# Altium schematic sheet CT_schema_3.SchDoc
size 411 x 401 mm
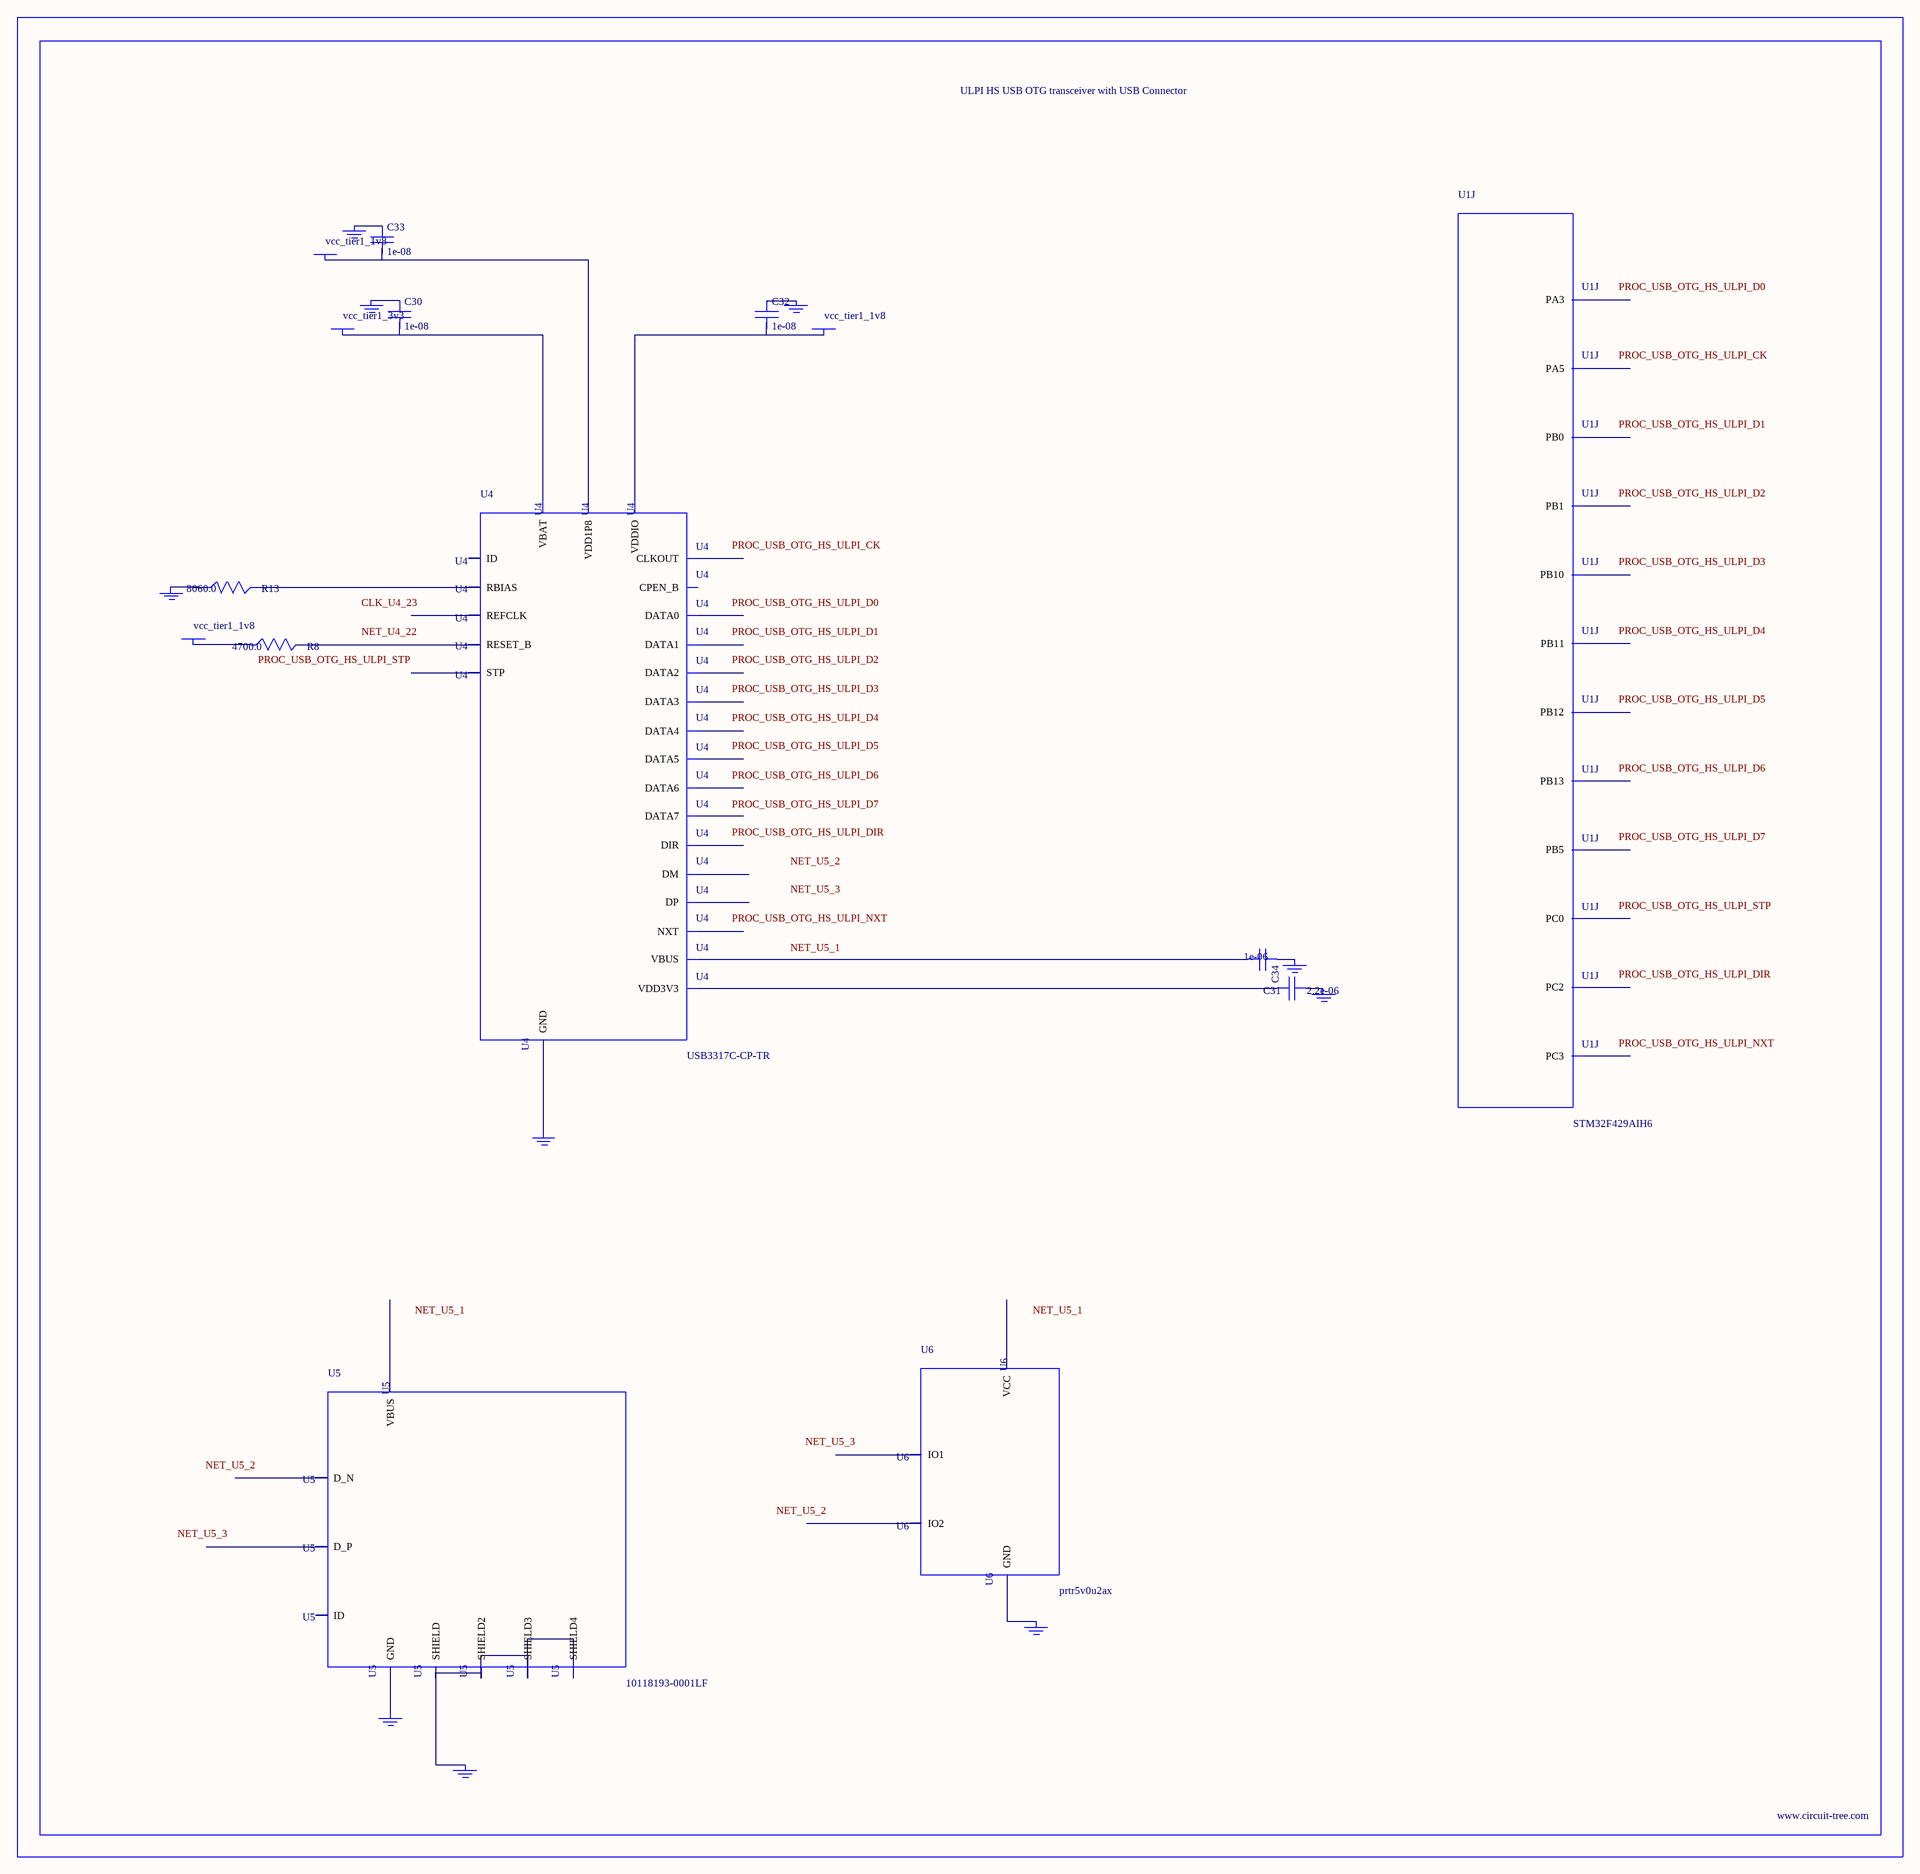
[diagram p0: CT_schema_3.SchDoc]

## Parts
BORDER2  (no value)
C30  1e-08  [C0402]
C31  2.2e-06  [C0603]
C32  1e-08  [C0402]
C33  1e-08  [C0402]
C34  1e-06  [C0603]
GND_INSTANCE_2_0  (no value)
GND_INSTANCE_2_1  (no value)
GND_INSTANCE_2_2  (no value)
GND_INSTANCE_2_3  (no value)
GND_INSTANCE_2_4  (no value)
GND_INSTANCE_2_5  (no value)
GND_INSTANCE_2_6  (no value)
GND_INSTANCE_2_7  (no value)
GND_INSTANCE_2_8  (no value)
GND_INSTANCE_2_9  (no value)
POWER_INSTANCE_2_0  vcc_tier1_3v3
POWER_INSTANCE_2_1  vcc_tier1_1v8
POWER_INSTANCE_2_2  vcc_tier1_1v8
POWER_INSTANCE_2_3  vcc_tier1_1v8
R8  4700.0  [R0603]
R13  8060.0  [R0603]
U1  STM32F429AIH6  [UFBGA169]  (part J of 12)
U4  USB3317C-CP-TR  [QFN-24]
U5  10118193-0001LF  [FCI_10118193-0001LF]
U6  prtr5v0u2ax  [SOT143B]

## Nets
NetC30_1: C30.1 GND_INSTANCE_2_1.0(GND)
NetC30_2: C30.2 POWER_INSTANCE_2_0.0(PWR) U4.3(VBAT)
NetC31_1: C31.1 GND_INSTANCE_2_2.0(GND)
NetC31_2: C31.2 U4.4(VDD3V3)
NetC32_1: C32.1 GND_INSTANCE_2_3.0(GND)
NetC32_2: C32.2 POWER_INSTANCE_2_1.0(PWR) U4.17(VDDIO)
NetC33_1: C33.1 GND_INSTANCE_2_4.0(GND)
NetC33_2: C33.2 POWER_INSTANCE_2_2.0(PWR) U4.21(VDD1P8)
NetC34_1: C34.1 GND_INSTANCE_2_0.0(GND)
NetC34_2: C34.2 U4.2(VBUS)
NetGND_INSTANCE_2_5_0: GND_INSTANCE_2_5.0(GND) R13.1
NetGND_INSTANCE_2_6_0: GND_INSTANCE_2_6.0(GND) U4.25(GND)
NetGND_INSTANCE_2_7_0: GND_INSTANCE_2_7.0(GND) U5.6(SHIELD) U5.7(SHIELD2) U5.8(SHIELD3) U5.9(SHIELD4)
NetGND_INSTANCE_2_8_0: GND_INSTANCE_2_8.0(GND) U5.5(GND)
NetGND_INSTANCE_2_9_0: GND_INSTANCE_2_9.0(GND) U6.1(GND)
NetPOWER_INSTANCE_2_3_0: POWER_INSTANCE_2_3.0(PWR) R8.1
NetR8_2: R8.2 U4.22(RESET_B)
NetR13_2: R13.2 U4.24(RBIAS)

Not connected (* = marked no-connect by the designer): U1 D5(PB5) G6(PC0) H6(PC2) H7(PC3) K3(PA3) K5(PB1) L9(PB10) M3(PA5) M9(PB11) M12(PB13) N4(PB0) N12(PB12); U4 1(ID) 5(DM) 6(DP) 7(CPEN_B) 8(DATA7) 9(DATA6) 10(DATA5) 11(DATA4) 12(CLKOUT) 13(DATA3) 14(DATA2) 15(DATA1) 16(DATA0) 18(NXT) 19(DIR) 20(STP) 23(REFCLK); U5 1(VBUS) 2(D_N) 3(D_P) 4(ID); U6 2(IO1) 3(IO2) 4(VCC)

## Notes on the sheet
- Labels drawn without touching a wire or pin: CLK_U4_23, NET_U4_22, NET_U5_1, NET_U5_2, NET_U5_3, PROC_USB_OTG_HS_ULPI_CK, PROC_USB_OTG_HS_ULPI_D0, PROC_USB_OTG_HS_ULPI_D1, PROC_USB_OTG_HS_ULPI_D2, PROC_USB_OTG_HS_ULPI_D3, PROC_USB_OTG_HS_ULPI_D4, PROC_USB_OTG_HS_ULPI_D5, PROC_USB_OTG_HS_ULPI_D6, PROC_USB_OTG_HS_ULPI_D7, PROC_USB_OTG_HS_ULPI_DIR, PROC_USB_OTG_HS_ULPI_NXT, PROC_USB_OTG_HS_ULPI_STP

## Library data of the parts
BORDER2 = BORDER_PAGE2
C30 C32 C33 = C0402C103K3RAC
C31 = C0603C225K8RACTU
C34 = C0603C105K3RACTU
GND_INSTANCE_2_0-GND_INSTANCE_2_9 = GND
POWER_INSTANCE_2_0-POWER_INSTANCE_2_3 = PWR
R8 = RC0603JR-074K7L
R13 = ERJ-3EKF8061V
